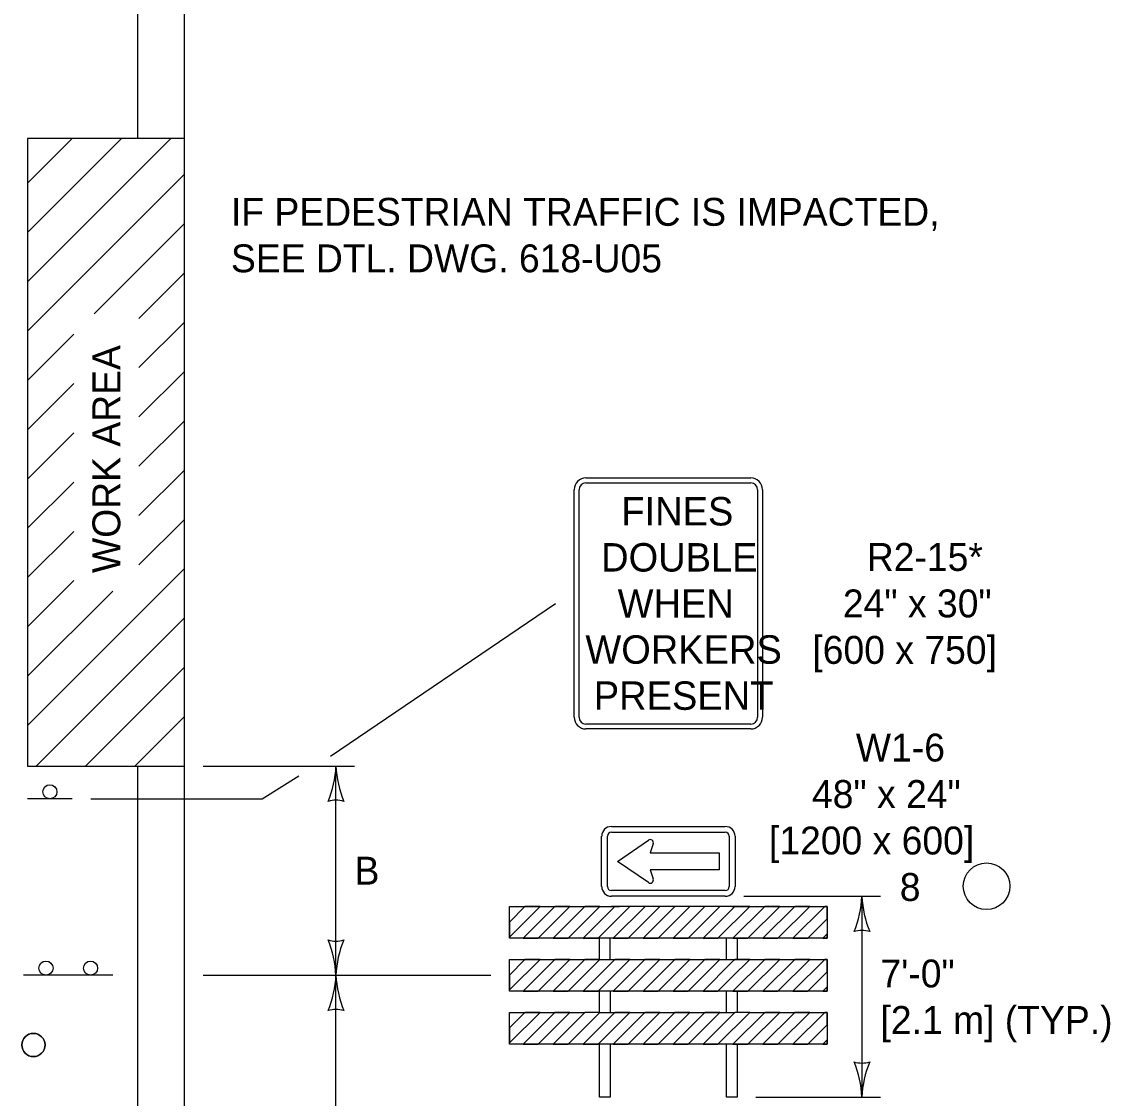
# Model space of a CAD drawing. Extents: x 49991.4 to 50021, y 49987.6 to 50011.4.
# Drawn here: x 50002.651 to 50004.993, y 50003.757 to 50006.073 of the extents above; entities that cross this region are included whole.
import ezdxf

# ---------------------------------------------------------------- set-up
doc = ezdxf.new("R2010")
doc.units = 0
for name, color, linetype in [('Level 1', 7, 'Continuous'), ('Level 2', 7, 'Continuous'), ('Level 3', 7, 'Continuous')]:
    doc.layers.add(name, color=color, linetype=linetype)

msp = doc.modelspace()

# ---------------------------------------------------------------- linework, layer by layer
at = {"layer": 'Level 1'}
for p, q in [((50002.901, 50005.8214), (50002.901, 50010.7538)), ((50003.001, 50000.5714), (50003.001, 50010.7538)), ((50002.6635, 50005.8214), (50002.6635, 50004.4714)), ((50002.6635, 50005.5134), (50002.9715, 50005.8214)), ((50002.6635, 50005.6194), (50002.8654, 50005.8214)), ((50002.6635, 50005.7255), (50002.7594, 50005.8214)), ((50003.001, 50005.8214), (50002.6635, 50005.8214)), ((50002.6635, 50005.4073), (50003.001, 50005.7448)), ((50002.8071, 50005.4448), (50003.001, 50005.6387)), ((50002.903, 50005.4347), (50003.001, 50005.5327)), ((50002.903, 50005.3287), (50003.001, 50005.4266)), ((50002.6635, 50005.3012), (50002.763, 50005.4008)), ((50002.903, 50005.2226), (50003.001, 50005.3205)), ((50002.6635, 50005.1952), (50002.763, 50005.2947)), ((50002.903, 50005.1165), (50003.001, 50005.2145)), ((50002.6635, 50005.0891), (50002.763, 50005.1887)), ((50002.903, 50005.0105), (50003.001, 50005.1084)), ((50002.6635, 50004.983), (50002.763, 50005.0826)), ((50003.8649, 50005.0914), (50004.2194, 50005.0914)), ((50004.0421, 50005.0914), (50004.0421, 50005.0914)), ((50003.8396, 50004.5767), (50003.8396, 50005.0661)), ((50003.8502, 50004.5767), (50003.8502, 50005.0661)), ((50003.8649, 50005.0809), (50004.2194, 50005.0809)), ((50004.2341, 50005.0661), (50004.2341, 50004.5767)), ((50004.2447, 50005.0661), (50004.2447, 50004.5767)), ((50002.903, 50004.9044), (50003.001, 50005.0023)), ((50002.6635, 50004.877), (50002.763, 50004.9765)), ((50002.6635, 50004.5588), (50003.001, 50004.8963)), ((50002.6635, 50004.7709), (50002.763, 50004.8705)), ((50002.6635, 50004.6648), (50002.8466, 50004.8479)), ((50002.6822, 50004.4714), (50003.001, 50004.7902)), ((50002.7882, 50004.4714), (50003.001, 50004.6841)), ((50002.8943, 50004.4714), (50003.001, 50004.5781)), ((50004.2194, 50004.5619), (50003.8649, 50004.5619)), ((50004.2194, 50004.5514), (50003.8649, 50004.5514)), ((50002.6635, 50004.4714), (50003.001, 50004.4714)), ((50002.901, 50000.5714), (50002.901, 50004.4714)), ((50003.0004, 50004.4714), (50003.001, 50004.472)), ((50002.7595, 50004.4009), (50002.6635, 50004.4009)), ((50003.9196, 50004.3415), (50004.1647, 50004.3415)), ((50003.8986, 50004.2123), (50003.8986, 50004.3206)), ((50003.911, 50004.2123), (50003.911, 50004.3206)), ((50003.9196, 50004.3291), (50004.1647, 50004.3291)), ((50003.9326, 50004.2664), (50003.9991, 50004.3121)), ((50004.1732, 50004.3206), (50004.1732, 50004.2123)), ((50004.1856, 50004.3206), (50004.1856, 50004.2123)), ((50004.0097, 50004.3042), (50004.0033, 50004.2847)), ((50003.9991, 50004.2207), (50003.9326, 50004.2664)), ((50004.0033, 50004.2847), (50004.0135, 50004.2847)), ((50004.0135, 50004.2847), (50004.1516, 50004.2847)), ((50004.1516, 50004.2847), (50004.1516, 50004.2482)), ((50004.1516, 50004.2482), (50004.0033, 50004.2482)), ((50004.0033, 50004.2482), (50004.0097, 50004.2286)), ((50004.1647, 50004.2037), (50003.9196, 50004.2037)), ((50003.7001, 50004.1037), (50003.766, 50004.1695)), ((50003.7001, 50004.1359), (50003.7337, 50004.1695)), ((50003.7337, 50004.1695), (50003.7001, 50004.1359)), ((50003.7001, 50004.1037), (50003.766, 50004.1695)), ((50003.7298, 50004.1011), (50003.7982, 50004.1695)), ((50003.7982, 50004.1695), (50003.7298, 50004.1011)), ((50003.762, 50004.1011), (50003.8304, 50004.1695)), ((50003.762, 50004.1011), (50003.8304, 50004.1695)), ((50003.7943, 50004.1011), (50003.8627, 50004.1695)), ((50003.8627, 50004.1695), (50003.7943, 50004.1011)), ((50003.8265, 50004.1011), (50003.8949, 50004.1695)), ((50003.8265, 50004.1011), (50003.8949, 50004.1695)), ((50003.8588, 50004.1011), (50003.9272, 50004.1695)), ((50003.891, 50004.1011), (50003.9594, 50004.1695)), ((50003.9053, 50004.1695), (50003.9367, 50004.1695)), ((50004.1647, 50004.1913), (50003.9196, 50004.1913)), ((50004.1647, 50004.1695), (50003.9196, 50004.1695)), ((50003.9235, 50004.1011), (50003.9919, 50004.1695)), ((50003.9557, 50004.1011), (50004.0241, 50004.1695)), ((50003.9879, 50004.1011), (50004.0563, 50004.1695)), ((50004.0201, 50004.1011), (50004.0885, 50004.1695)), ((50004.0523, 50004.1011), (50004.1207, 50004.1695)), ((50004.0845, 50004.1011), (50004.1529, 50004.1695)), ((50004.1167, 50004.1011), (50004.1851, 50004.1695)), ((50004.1851, 50004.1695), (50004.1452, 50004.1695)), ((50004.1489, 50004.1011), (50004.2173, 50004.1695)), ((50004.1812, 50004.1011), (50004.2496, 50004.1695)), ((50004.2496, 50004.1695), (50004.1812, 50004.1011)), ((50004.2134, 50004.1011), (50004.2818, 50004.1695)), ((50004.2134, 50004.1011), (50004.2818, 50004.1695)), ((50004.2456, 50004.1011), (50004.314, 50004.1695)), ((50004.314, 50004.1695), (50004.2456, 50004.1011)), ((50004.2779, 50004.1011), (50004.3463, 50004.1695)), ((50004.2779, 50004.1011), (50004.3463, 50004.1695)), ((50004.3102, 50004.1011), (50004.3786, 50004.1695)), ((50004.3786, 50004.1695), (50004.3102, 50004.1011)), ((50004.3424, 50004.1011), (50004.3841, 50004.1429)), ((50004.3424, 50004.1011), (50004.3841, 50004.1429)), ((50003.9167, 50004.0556), (50003.9167, 50004.1011)), ((50004.1675, 50004.0556), (50004.1675, 50004.1011)), ((50004.3746, 50004.1011), (50004.3841, 50004.1106)), ((50004.3841, 50004.1106), (50004.3746, 50004.1011)), ((50003.7001, 50003.9897), (50003.766, 50004.0556)), ((50003.7001, 50004.0219), (50003.7337, 50004.0556)), ((50003.7337, 50004.0556), (50003.7001, 50004.0219)), ((50003.7001, 50003.9897), (50003.766, 50004.0556)), ((50003.7298, 50003.9872), (50003.7982, 50004.0556)), ((50003.7982, 50004.0556), (50003.7298, 50003.9872)), ((50003.762, 50003.9872), (50003.8304, 50004.0556)), ((50003.762, 50003.9872), (50003.8304, 50004.0556)), ((50003.7943, 50003.9872), (50003.8627, 50004.0556)), ((50003.8627, 50004.0556), (50003.7943, 50003.9872)), ((50003.8265, 50003.9872), (50003.8949, 50004.0556)), ((50003.8265, 50003.9872), (50003.8949, 50004.0556)), ((50003.8588, 50003.9872), (50003.9272, 50004.0556)), ((50003.891, 50003.9872), (50003.9594, 50004.0556)), ((50003.9232, 50003.9872), (50003.9916, 50004.0556)), ((50003.9555, 50003.9872), (50004.0239, 50004.0556)), ((50003.9877, 50003.9872), (50004.0561, 50004.0556)), ((50004.02, 50003.9872), (50004.0884, 50004.0556)), ((50004.0522, 50003.9872), (50004.1206, 50004.0556)), ((50004.0844, 50003.9872), (50004.1528, 50004.0556)), ((50004.1789, 50004.0172), (50004.2173, 50004.0556)), ((50004.1789, 50004.0494), (50004.1851, 50004.0556)), ((50004.1812, 50003.9872), (50004.2496, 50004.0556)), ((50004.2496, 50004.0556), (50004.1812, 50003.9872)), ((50004.2134, 50003.9872), (50004.2818, 50004.0556)), ((50004.2134, 50003.9872), (50004.2818, 50004.0556)), ((50004.2456, 50003.9872), (50004.314, 50004.0556)), ((50004.314, 50004.0556), (50004.2456, 50003.9872)), ((50004.2779, 50003.9872), (50004.3463, 50004.0556)), ((50004.2779, 50003.9872), (50004.3463, 50004.0556)), ((50004.3102, 50003.9872), (50004.3786, 50004.0556)), ((50004.3786, 50004.0556), (50004.3102, 50003.9872)), ((50004.1167, 50003.9872), (50004.1789, 50004.0494)), ((50004.3424, 50003.9872), (50004.3841, 50004.0289)), ((50004.3424, 50003.9872), (50004.3841, 50004.0289)), ((50002.751, 50004.0214), (50002.655, 50004.0214)), ((50002.847, 50004.0214), (50002.751, 50004.0214)), ((50004.1489, 50003.9872), (50004.1789, 50004.0172)), ((50004.3746, 50003.9872), (50004.3841, 50003.9967)), ((50004.3841, 50003.9967), (50004.3746, 50003.9872)), ((50003.7001, 50003.8757), (50003.766, 50003.9416)), ((50003.7001, 50003.908), (50003.7337, 50003.9416)), ((50003.7337, 50003.9416), (50003.7001, 50003.908)), ((50003.7001, 50003.8757), (50003.766, 50003.9416)), ((50003.7298, 50003.8732), (50003.7982, 50003.9416)), ((50003.7982, 50003.9416), (50003.7298, 50003.8732)), ((50003.762, 50003.8732), (50003.8304, 50003.9416)), ((50003.762, 50003.8732), (50003.8304, 50003.9416)), ((50003.7943, 50003.8732), (50003.8627, 50003.9416)), ((50003.8627, 50003.9416), (50003.7943, 50003.8732)), ((50003.8265, 50003.8732), (50003.8949, 50003.9416)), ((50003.8265, 50003.8732), (50003.8949, 50003.9416)), ((50003.8588, 50003.8732), (50003.9272, 50003.9416)), ((50003.9272, 50003.9416), (50003.8588, 50003.8732)), ((50003.891, 50003.8732), (50003.9594, 50003.9416)), ((50003.891, 50003.8732), (50003.9594, 50003.9416)), ((50003.9232, 50003.8732), (50003.9916, 50003.9416)), ((50003.9916, 50003.9416), (50003.9232, 50003.8732)), ((50003.9555, 50003.8732), (50004.0239, 50003.9416)), ((50003.9555, 50003.8732), (50004.0239, 50003.9416)), ((50003.9877, 50003.8732), (50004.0561, 50003.9416)), ((50004.0561, 50003.9416), (50003.9877, 50003.8732)), ((50004.02, 50003.8732), (50004.0884, 50003.9416)), ((50004.02, 50003.8732), (50004.0884, 50003.9416)), ((50004.0522, 50003.8732), (50004.1206, 50003.9416)), ((50004.1206, 50003.9416), (50004.0522, 50003.8732)), ((50004.0844, 50003.8732), (50004.1528, 50003.9416)), ((50004.0844, 50003.8732), (50004.1528, 50003.9416)), ((50004.1167, 50003.8732), (50004.1851, 50003.9416)), ((50004.1851, 50003.9416), (50004.1167, 50003.8732)), ((50004.1489, 50003.8732), (50004.2173, 50003.9416)), ((50004.1489, 50003.8732), (50004.2173, 50003.9416)), ((50004.1812, 50003.8732), (50004.2496, 50003.9416)), ((50004.2496, 50003.9416), (50004.1812, 50003.8732)), ((50004.2134, 50003.8732), (50004.2818, 50003.9416)), ((50004.2134, 50003.8732), (50004.2818, 50003.9416)), ((50004.2456, 50003.8732), (50004.314, 50003.9416)), ((50004.314, 50003.9416), (50004.2456, 50003.8732)), ((50004.2779, 50003.8732), (50004.3463, 50003.9416)), ((50004.2779, 50003.8732), (50004.3463, 50003.9416)), ((50004.3102, 50003.8732), (50004.3786, 50003.9416)), ((50004.3786, 50003.9416), (50004.3102, 50003.8732)), ((50004.3424, 50003.8732), (50004.3841, 50003.915)), ((50004.3424, 50003.8732), (50004.3841, 50003.915)), ((50004.3746, 50003.8732), (50004.3841, 50003.8827)), ((50004.3841, 50003.8827), (50004.3746, 50003.8732))]:
    msp.add_line(p, q, dxfattribs=at)
for points in [[(50004.1789, 50004.1011), (50003.7001, 50004.1011), (50003.7001, 50004.1695), (50003.9053, 50004.1695)], [(50003.766, 50004.1695), (50003.7337, 50004.1695)], [(50003.8304, 50004.1695), (50003.7982, 50004.1695)], [(50003.9594, 50004.1695), (50003.9367, 50004.1695), (50003.9272, 50004.1695), (50003.8588, 50004.1011), (50003.891, 50004.1011), (50003.9594, 50004.1695)], [(50003.8949, 50004.1695), (50003.8627, 50004.1695)], [(50004.0241, 50004.1695), (50003.9919, 50004.1695), (50003.9235, 50004.1011), (50003.9557, 50004.1011), (50004.0241, 50004.1695)], [(50004.0885, 50004.1695), (50004.0563, 50004.1695), (50003.9879, 50004.1011), (50004.0201, 50004.1011), (50004.0885, 50004.1695)], [(50004.1529, 50004.1695), (50004.1452, 50004.1695), (50004.1207, 50004.1695), (50004.0523, 50004.1011), (50004.0845, 50004.1011), (50004.1529, 50004.1695)], [(50004.1167, 50004.1011), (50004.1489, 50004.1011), (50004.2173, 50004.1695), (50004.1851, 50004.1695), (50004.1167, 50004.1011)], [(50004.1789, 50004.1695), (50004.3841, 50004.1695), (50004.3841, 50004.1011), (50004.1789, 50004.1011)], [(50004.2818, 50004.1695), (50004.2496, 50004.1695)], [(50004.3463, 50004.1695), (50004.314, 50004.1695)], [(50004.3841, 50004.1429), (50004.3841, 50004.1695), (50004.3786, 50004.1695)], [(50003.7001, 50004.1359), (50003.7001, 50004.1037)], [(50003.7298, 50004.1011), (50003.762, 50004.1011)], [(50003.7943, 50004.1011), (50003.8265, 50004.1011)], [(50003.8939, 50004.0555), (50003.8939, 50004.1011)], [(50004.1812, 50004.1011), (50004.2134, 50004.1011)], [(50004.1903, 50004.1011), (50004.1903, 50004.0556)], [(50004.2456, 50004.1011), (50004.2779, 50004.1011)], [(50004.3102, 50004.1011), (50004.3424, 50004.1011)], [(50004.3746, 50004.1011), (50004.3841, 50004.1011), (50004.3841, 50004.1106)], [(50004.1789, 50004.0556), (50004.3841, 50004.0556), (50004.3841, 50003.9872), (50003.7001, 50003.9872), (50003.7001, 50004.0556), (50004.1789, 50004.0556)], [(50003.766, 50004.0556), (50003.7337, 50004.0556)], [(50003.8304, 50004.0556), (50003.7982, 50004.0556)], [(50003.9594, 50004.0556), (50003.9272, 50004.0556), (50003.8588, 50003.9872), (50003.891, 50003.9872), (50003.9594, 50004.0556)], [(50003.8949, 50004.0556), (50003.8627, 50004.0556)], [(50004.0239, 50004.0556), (50003.9916, 50004.0556), (50003.9232, 50003.9872), (50003.9555, 50003.9872), (50004.0239, 50004.0556)], [(50004.0884, 50004.0556), (50004.0561, 50004.0556), (50003.9877, 50003.9872), (50004.02, 50003.9872), (50004.0884, 50004.0556)], [(50004.1528, 50004.0556), (50004.1206, 50004.0556), (50004.0522, 50003.9872), (50004.0844, 50003.9872), (50004.1528, 50004.0556)], [(50004.1167, 50003.9872), (50004.1489, 50003.9872), (50004.1789, 50004.0172), (50004.2173, 50004.0556), (50004.1903, 50004.0556), (50004.1851, 50004.0556), (50004.1789, 50004.0494), (50004.1167, 50003.9872)], [(50004.2818, 50004.0556), (50004.2496, 50004.0556)], [(50004.3463, 50004.0556), (50004.314, 50004.0556)], [(50004.3841, 50004.0289), (50004.3841, 50004.0556), (50004.3786, 50004.0556)], [(50003.7001, 50004.0219), (50003.7001, 50003.9897)], [(50003.7298, 50003.9872), (50003.762, 50003.9872)], [(50003.7943, 50003.9872), (50003.8265, 50003.9872)], [(50003.8939, 50003.9416), (50003.8939, 50003.9872)], [(50003.9167, 50003.9872), (50003.9167, 50003.9416)], [(50004.1675, 50003.9416), (50004.1675, 50003.9872)], [(50004.1812, 50003.9872), (50004.2134, 50003.9872)], [(50004.1903, 50003.9872), (50004.1903, 50003.9416)], [(50004.2456, 50003.9872), (50004.2779, 50003.9872)], [(50004.3102, 50003.9872), (50004.3424, 50003.9872)], [(50004.3746, 50003.9872), (50004.3841, 50003.9872), (50004.3841, 50003.9967)], [(50004.2173, 50003.9416), (50004.3841, 50003.9416), (50004.3841, 50003.8732), (50003.7001, 50003.8732), (50003.7001, 50003.9416), (50003.8627, 50003.9416)], [(50003.766, 50003.9416), (50003.7337, 50003.9416)], [(50003.8304, 50003.9416), (50003.7982, 50003.9416)], [(50003.8949, 50003.9416), (50003.8627, 50003.9416)], [(50003.8949, 50003.9416), (50004.1851, 50003.9416)], [(50003.9594, 50003.9416), (50003.9272, 50003.9416)], [(50004.0239, 50003.9416), (50003.9916, 50003.9416)], [(50004.0884, 50003.9416), (50004.0561, 50003.9416)], [(50004.1528, 50003.9416), (50004.1206, 50003.9416)], [(50004.2173, 50003.9416), (50004.1851, 50003.9416)], [(50004.2818, 50003.9416), (50004.2496, 50003.9416)], [(50004.3463, 50003.9416), (50004.314, 50003.9416)], [(50004.3841, 50003.915), (50004.3841, 50003.9416), (50004.3786, 50003.9416)], [(50003.7001, 50003.908), (50003.7001, 50003.8757)], [(50003.7298, 50003.8732), (50003.762, 50003.8732)], [(50003.7943, 50003.8732), (50003.8265, 50003.8732)], [(50003.8588, 50003.8732), (50003.891, 50003.8732)], [(50003.9167, 50003.8731), (50003.9167, 50003.7591), (50003.8939, 50003.7591), (50003.8939, 50003.8731)], [(50003.9232, 50003.8732), (50003.9555, 50003.8732)], [(50003.9877, 50003.8732), (50004.02, 50003.8732)], [(50004.0522, 50003.8732), (50004.0844, 50003.8732)], [(50004.1167, 50003.8732), (50004.1489, 50003.8732)], [(50004.1903, 50003.8731), (50004.1903, 50003.7591), (50004.1675, 50003.7591), (50004.1675, 50003.8731)], [(50004.1812, 50003.8732), (50004.2134, 50003.8732)], [(50004.2456, 50003.8732), (50004.2779, 50003.8732)], [(50004.3102, 50003.8732), (50004.3424, 50003.8732)], [(50004.3746, 50003.8732), (50004.3841, 50003.8732), (50004.3841, 50003.8827)]]:
    msp.add_lwpolyline(points, dxfattribs=at)
for centre, radius in [((50002.7115, 50004.4162), 0.0152), ((50002.703, 50004.0367), 0.0152), ((50002.799, 50004.0367), 0.0152), ((50002.676, 50003.8714), 0.025)]:
    msp.add_circle(centre, radius, dxfattribs=at)
for centre, radius, start, end in [((50003.8649, 50005.0661), 0.0253, 90, 180), ((50004.2194, 50005.0661), 0.0253, 0, 90), ((50003.8649, 50005.0661), 0.0148, 90, 180), ((50004.2194, 50005.0661), 0.0148, 0, 90), ((50003.8649, 50004.5767), 0.0253, 180, 270), ((50003.8649, 50004.5767), 0.0148, 180, 270), ((50004.2194, 50004.5767), 0.0148, 270, 360), ((50004.2194, 50004.5767), 0.0253, 270, 360), ((50003.9196, 50004.3206), 0.0209, 90, 180), ((50004.1647, 50004.3206), 0.0209, 0, 90), ((50003.9196, 50004.3206), 0.00855, 90, 180), ((50004.003, 50004.3064), 0.00695, 342.0418, 124.5194), ((50004.1647, 50004.3206), 0.00855, 0, 90), ((50004.003, 50004.2264), 0.00695, 235.4806, 17.9582), ((50003.9196, 50004.2123), 0.0209, 180, 270), ((50003.9196, 50004.2123), 0.00855, 180, 270), ((50004.1647, 50004.2123), 0.00855, 270, 0), ((50004.1647, 50004.2123), 0.0209, 270, 0), ((50002.676, 50003.8714), 0.025, 0, 180), ((50002.676, 50003.8714), 0.025, 180, 0)]:
    msp.add_arc(centre, radius, start, end, dxfattribs=at)
at = {"layer": 'Level 2'}
msp.add_circle((50004.7268, 50004.2129), 0.0501, dxfattribs=at)
at = {"layer": 'Level 3'}
for p, q in [((50003.3152, 50004.4925), (50003.7996, 50004.8214)), ((50003.041, 50004.4714), (50003.367, 50004.4714)), ((50003.1681, 50004.4009), (50003.2473, 50004.4502)), ((50003.327, 50004.0214), (50003.327, 50004.4714)), ((50002.7995, 50004.4009), (50003.1681, 50004.4009)), ((50004.2047, 50004.1913), (50004.4985, 50004.1913)), ((50004.4585, 50004.1913), (50004.4585, 50003.7591)), ((50003.041, 50004.0214), (50003.6601, 50004.0214)), ((50003.327, 50003.4214), (50003.327, 50004.0214)), ((50004.2303, 50003.7591), (50004.4985, 50003.7591))]:
    msp.add_line(p, q, dxfattribs=at)
for centre, radius, start, end in [((50003.1049, 50004.4805), 0.2223, 337.456, 357.6395), ((50003.5597, 50004.4829), 0.233, 182.8273, 202.0772), ((50003.327, 50004.3432), 0.0548, 72.1388, 107.8612), ((50004.2364, 50004.2005), 0.2223, 337.456, 357.6395), ((50004.6912, 50004.2028), 0.233, 182.8273, 202.0772), ((50004.4585, 50004.0631), 0.0548, 72.1388, 107.8612), ((50003.327, 50004.1496), 0.0548, 252.1388, 287.8612), ((50003.0943, 50004.0099), 0.233, 2.8273, 22.0772), ((50003.5491, 50004.0122), 0.2223, 157.456, 177.6395), ((50003.1049, 50004.0305), 0.2223, 337.456, 357.6395), ((50003.5597, 50004.0329), 0.233, 182.8273, 202.0772), ((50003.327, 50003.8932), 0.0548, 72.1388, 107.8612), ((50004.4585, 50003.8873), 0.0548, 252.1388, 287.8612), ((50004.2258, 50003.7476), 0.233, 2.8273, 22.0772), ((50004.6806, 50003.75), 0.2223, 157.456, 177.6395)]:
    msp.add_arc(centre, radius, start, end, dxfattribs=at)

# ---------------------------------------------------------------- texts
at = {"layer": 'Level 1'}
for s, p in [('FINES', (50003.941, 50004.9891)), ('DOUBLE', (50003.8975, 50004.89)), ('WHEN ', (50003.933, 50004.7908)), ('WORKERS', (50003.8636, 50004.6917)), ('PRESENT', (50003.8817, 50004.5925))]:
    msp.add_text(s, height=0.06118, dxfattribs=at).set_placement(p)
at = {"layer": 'Level 2'}
for s, p in [('IF PEDESTRIAN TRAFFIC IS IMPACTED,', (50003.101, 50005.6339)), ('SEE DTL. DWG. 618-U05', (50003.101, 50005.5339)), ('R2-15*', (50004.4691, 50004.8914)), ('24" x 30"', (50004.4176, 50004.7914)), ('[600 x 750]', (50004.352, 50004.6914)), ('W1-6', (50004.4455, 50004.4813)), ('48" x 24"', (50004.3511, 50004.3813)), ('[1200 x 600]', (50004.2586, 50004.2813)), ('B', (50003.367, 50004.2164)), ('        8', (50004.3617, 50004.1813)), ('7\'-0" ', (50004.4985, 50003.9952)), ('[2.1 m] (TYP.)', (50004.4985, 50003.8952))]:
    msp.add_text(s, height=0.06, dxfattribs=at).set_placement(p)
msp.add_text('WORK AREA', height=0.06, rotation=90, dxfattribs=at).set_placement((50002.863, 50004.8868))

doc.saveas('drawing.dxf')
